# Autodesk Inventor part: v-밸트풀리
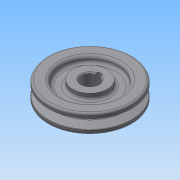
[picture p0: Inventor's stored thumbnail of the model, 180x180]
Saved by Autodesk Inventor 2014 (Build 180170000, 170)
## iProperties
Created: 2018-12
Part Number: v-밸트풀리
Material: Generic
Document SubType Name: Modeling
Designer: HI
Density: 1 g/cm^3
Appearance: Default
Author: HI
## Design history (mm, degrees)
sketch "Sketch1"
  geometry: L1 (0, 9.5)-(0, -9.5); L2 (42.7, 4.877)-(33.7, 1.953); L3 (33.7, 1.953)-(33.7, 0); L4 (42.7, -4.877)-(33.7, -1.953); L5 (33.7, -1.953)-(33.7, 0); L6 (29, -3.5)-(29, -9.5); L7 (29, -3.5)-(17.5, -3.5); L8 (17.5, -3.5)-(17.5, -9.5); L9 (29, 3.5)-(29, 9.5); L10 (29, 3.5)-(17.5, 3.5); L11 (17.5, 3.5)-(17.5, 9.5); L12 (42.7, 9.5)-(42.7, 4.877); L13 (42.7, -4.877)-(42.7, -9.5); L14 (0, 9.5)-(17.5, 9.5); L15 (29, 9.5)-(42.7, 9.5); L16 (42.7, -9.5)-(29, -9.5); L17 (17.5, -9.5)-(0, -9.5); 1 further point
  constraints: 34 end point, 8 perpendicular, 4 parallel, 1 vertical
  dimensions: "d0" = 19 distance of L1.start L1.end; "d6" = 35 diameter of L8 L1; "d7" = 58 diameter of L6 L1
revolve "Revolution1" sketch "Sketch1" stored, may be unused: angle "d9" = 90 deg
sketch "Sketch2"
  geometry: L1 (-2.5, 10.8)-(2.5, 10.8); L2 (2.5, 10.8)-(2.5, 8.124); L3 (-2.5, 8.124)-(-2.5, 10.8); C1 r 17.5 at (0, 0) reference; A1 r 8.5 centre (0, 0) between (-2.5, 8.124) and (2.5, 8.124)
  constraints: 6 end point, 2 point on circle, 1 centre point, 1 coincident, 1 horizontal, 1 parallel, 1 perpendicular
  dimensions: "d10" = 17 diameter of A1
extrude "Extrusion1" cut sketch "Sketch2" stored distance "d14" = 10; taper "d15" = 0 deg
fillet "Fillet1" dims "d16" = 0.5
fillet "Fillet2" dims "d17" = 1
fillet "Fillet3" dims "d18" = 2
chamfer "Chamfer1" distance "d19" = 1; stored, may be unused: second distance "d20" = 2, angle "d21" = 45 deg
fillet "Fillet4" dims "d22" = 3
body "Solid1"
other parameters: "d2" = 85.4, "d4" = 6.3, "d8" = 6
